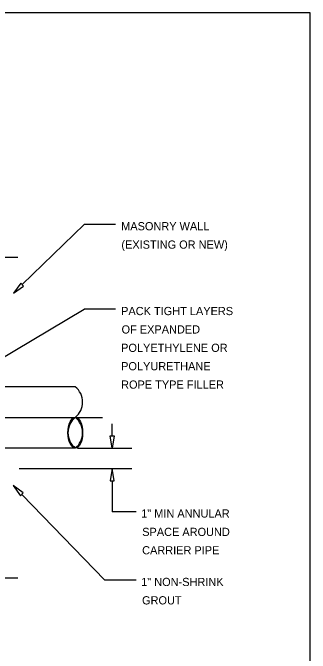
# Model space of a CAD drawing. Extents: x 2147138 to 2147698, y 2147153 to 2147515.
# Drawn here: x 2147246.9 to 2147290.5, y 2147250.3 to 2147344.1 of the extents above; entities that cross this region are included whole.
import ezdxf

# ---------------------------------------------------------------- set-up
doc = ezdxf.new("R2010")
doc.units = 0
for name, color, linetype in [('1', 7, 'Continuous'), ('G-ANNO-SYMB', 7, 'Continuous'), ('G-DETL-ANNO-LW10', 7, 'Continuous'), ('G-DETL-CNTR', 7, 'Continuous'), ('G-DETL-LW10', 7, 'Continuous'), ('PATTERN_CLASS', 7, 'Continuous')]:
    doc.layers.add(name, color=color, linetype=linetype)

msp = doc.modelspace()

# ---------------------------------------------------------------- linework, layer by layer
at = {"layer": '1'}
msp.add_ellipse((2147256.058, 2147282.556), major_axis=(0, -2.25), ratio=0.476405, dxfattribs=at)
at = {"layer": 'G-ANNO-SYMB'}
for p, q in [((2147231.08, 2147308.294), (2147247.627, 2147308.294)), ((2147231.08, 2147261.318), (2147247.627, 2147261.318))]:
    msp.add_line(p, q, dxfattribs=at)
at = {"layer": 'G-DETL-ANNO-LW10'}
for p, q in [((2147248.279, 2147304.285), (2147257.364, 2147313.105)), ((2147261.966, 2147313.105), (2147257.364, 2147313.105)), ((2147243.945, 2147292.72), (2147257.364, 2147300.671)), ((2147261.966, 2147300.671), (2147257.364, 2147300.671)), ((2147261.451, 2147282.098), (2147261.451, 2147283.89)), ((2147256.388, 2147280.306), (2147264.331, 2147280.306)), ((2147247.827, 2147277.318), (2147264.331, 2147277.318)), ((2147261.451, 2147275.526), (2147261.451, 2147270.97)), ((2147248.218, 2147273.528), (2147260.378, 2147260.959)), ((2147264.981, 2147270.97), (2147261.451, 2147270.97)), ((2147264.981, 2147260.959), (2147260.378, 2147260.959))]:
    msp.add_line(p, q, dxfattribs=at)
for points in [[(2147248.487, 2147304.071), (2147248.071, 2147304.499), (2147246.993, 2147303.037)], [(2147261.153, 2147282.098), (2147261.75, 2147282.098), (2147261.451, 2147280.306)], [(2147261.153, 2147275.526), (2147261.75, 2147275.526), (2147261.451, 2147277.318)], [(2147248.003, 2147273.321), (2147248.432, 2147273.736), (2147246.972, 2147274.816)]]:
    msp.add_lwpolyline(points, close=True, dxfattribs=at)
at = {"layer": 'G-DETL-CNTR'}
msp.add_line((2147200.1, 2147284.806), (2147260.058, 2147284.806), dxfattribs=at)
at = {"layer": 'G-DETL-LW10'}
for p, q in [((2147256.058, 2147289.306), (2147204.1, 2147289.306)), ((2147256.058, 2147280.306), (2147204.1, 2147280.306))]:
    msp.add_line(p, q, dxfattribs=at)
for centre, start, end in [((2147254.232, 2147287.056), 309.05324, 50.94676), ((2147257.883, 2147282.556), 129.05324, 230.94676), ((2147254.232, 2147282.556), 309.05324, 50.94676)]:
    msp.add_arc(centre, 2.897, start, end, dxfattribs=at)
at = {"layer": 'PATTERN_CLASS'}
for p, q in [((2147290.476, 2147344.122), (2147166.29, 2147344.122)), ((2147290.476, 2147191.852), (2147290.476, 2147344.122))]:
    msp.add_line(p, q, dxfattribs=at)

# ---------------------------------------------------------------- texts
at = {"layer": 'G-DETL-ANNO-LW10'}
for s, p in [('MASONRY WALL', (2147262.779, 2147312.241)), ('(EXISTING OR NEW)', (2147262.809, 2147309.546)), ('PACK TIGHT LAYERS', (2147262.772, 2147299.807)), ('OF EXPANDED', (2147262.837, 2147297.112)), ('POLYETHYLENE OR', (2147262.772, 2147294.417)), ('POLYURETHANE', (2147262.772, 2147291.722)), ('ROPE TYPE FILLER', (2147262.769, 2147289.027)), ('1" MIN ANNULAR', (2147265.716, 2147270.127)), ('SPACE AROUND', (2147265.859, 2147267.432)), ('CARRIER PIPE', (2147265.848, 2147264.738)), ('1" NON-SHRINK', (2147265.716, 2147260.094)), ('GROUT', (2147265.84, 2147257.399))]:
    msp.add_text(s, height=1.2, dxfattribs=at).set_placement(p)

doc.saveas('drawing.dxf')
